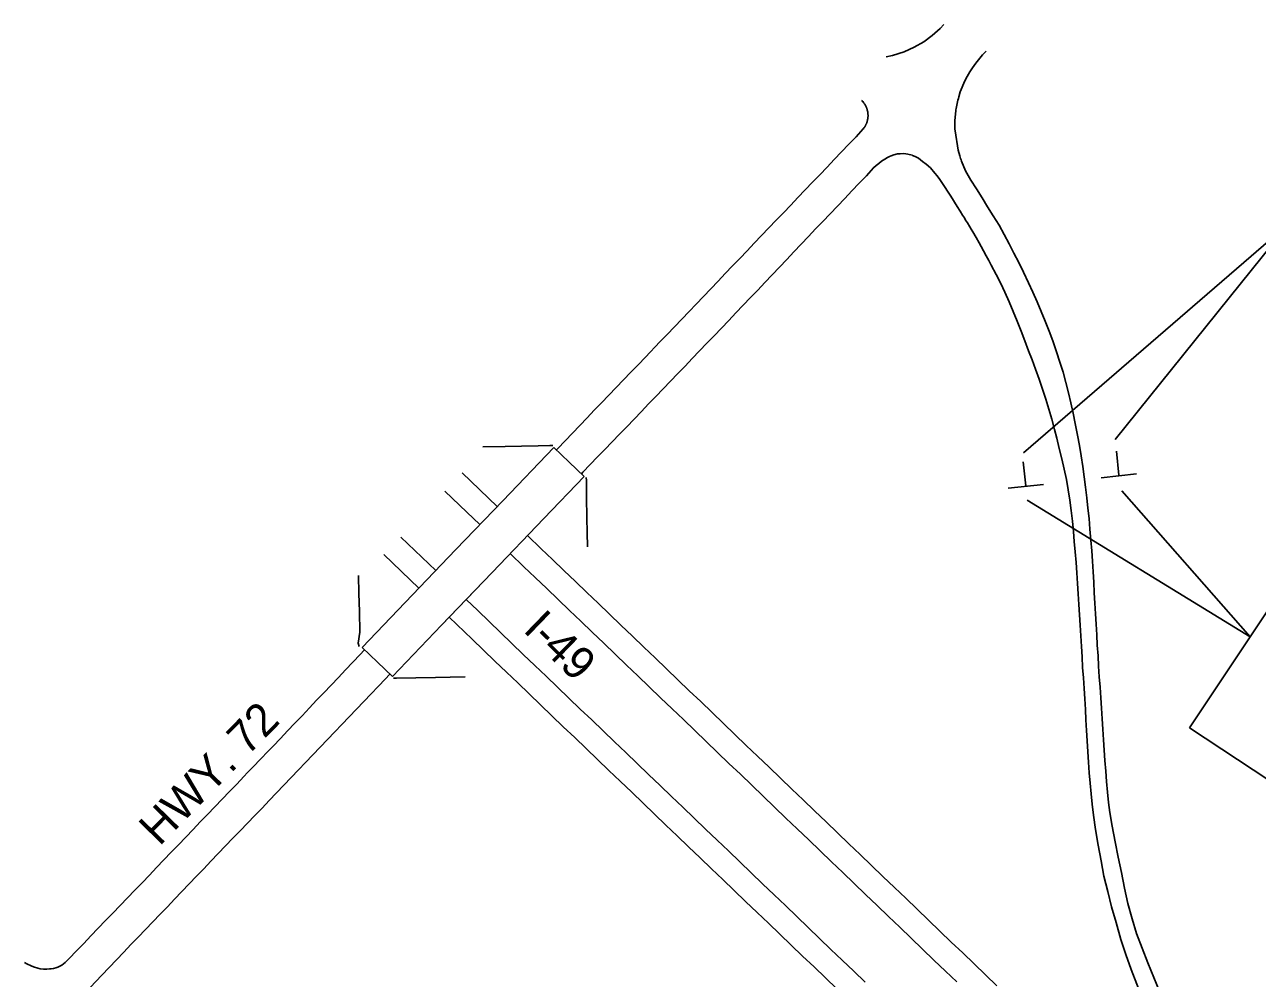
# Model space of a CAD drawing. Extents: x 1017892 to 1236694, y 658811 to 792468.
# Drawn here: x 1021447 to 1022033, y 660033 to 660486 of the extents above; entities that cross this region are included whole.
import ezdxf

# ---------------------------------------------------------------- set-up
doc = ezdxf.new("R2010")
doc.units = 0
for name, color, linetype in [('Level 3', 7, 'Continuous'), ('Level 8', 7, 'Continuous'), ('R_Proposed Road Annot', 7, 'Continuous'), ('S_BRIDGE', 7, 'Continuous'), ('S_CURB', 7, 'Continuous'), ('S_EDGE_PAVEMENT', 7, 'Continuous')]:
    doc.layers.add(name, color=color, linetype=linetype)

msp = doc.modelspace()

# ---------------------------------------------------------------- linework, layer by layer
at = {"layer": 'Level 3'}
for p, q in [((1021967.37, 660271.69), (1021966.17, 660283.15)), ((1021923.15, 660266.71), (1021921.9, 660278.16)), ((1021975.74, 660272.32), (1021958.96, 660270.57)), ((1021931.53, 660267.38), (1021914.75, 660265.54))]:
    msp.add_line(p, q, dxfattribs=at)
at = {"layer": 'Level 8'}
for p in [(1022058.32, 660238.1), (1022087.29, 660094.45)]:
    msp.add_line(p, (1022000.96, 660151.75), dxfattribs=at)
at = {"layer": 'R_Proposed Road Annot'}
for p, q in [((1021922.04, 660282.36), (1022048.03, 660391.35)), ((1021965.64, 660288.67), (1022048.03, 660391.35)), ((1021968.73, 660264.38), (1022029.64, 660194.93)), ((1021923.7, 660259.86), (1022029.64, 660194.93))]:
    msp.add_line(p, q, dxfattribs=at)
at = {"layer": 'S_BRIDGE'}
for p, q in [((1021698.82, 660284.98), (1021674.52, 660259.61)), ((1021698.82, 660284.98), (1021674.52, 660259.61)), ((1021706.09, 660277.95), (1021698.82, 660284.98)), ((1021706.09, 660277.95), (1021698.82, 660284.98)), ((1021713.21, 660271.18), (1021706.09, 660277.95)), ((1021713.21, 660271.18), (1021706.09, 660277.95)), ((1021694.12, 660251.24), (1021713.21, 660271.18)), ((1021694.12, 660251.24), (1021713.21, 660271.18)), ((1021674.52, 660259.61), (1021652.31, 660236.44)), ((1021674.52, 660259.61), (1021652.31, 660236.44)), ((1021669.48, 660225.51), (1021694.12, 660251.24)), ((1021669.48, 660225.51), (1021694.12, 660251.24)), ((1021652.31, 660236.44), (1021628.18, 660211.28)), ((1021652.31, 660236.44), (1021628.18, 660211.28)), ((1021645.49, 660200.48), (1021669.48, 660225.51)), ((1021657.16, 660212.65), (1021669.48, 660225.51)), ((1021628.18, 660211.28), (1021607.71, 660189.93)), ((1021628.18, 660211.28), (1021607.71, 660189.93)), ((1021645.49, 660200.48), (1021657.15, 660212.64)), ((1021622.15, 660176.11), (1021645.49, 660200.48)), ((1021622.15, 660176.11), (1021645.49, 660200.48)), ((1021607.71, 660189.93), (1021615.05, 660182.89)), ((1021607.71, 660189.93), (1021615.05, 660182.89)), ((1021615.05, 660182.89), (1021622.15, 660176.11)), ((1021615.05, 660182.89), (1021622.15, 660176.11))]:
    msp.add_line(p, q, dxfattribs=at)
at = {"layer": 'S_CURB'}
msp.add_line((1021606.62, 660197.13), (1021606.47, 660207.02), dxfattribs=at)
for points in [[(1021665.14, 660285.18), (1021675.69, 660285.41), (1021683.53, 660285.57), (1021691.36, 660285.73), (1021696.95, 660285.81), (1021698.32, 660285.85)], [(1021714.17, 660270.69), (1021714.28, 660269.21), (1021714.28, 660261.37), (1021714.44, 660251.56), (1021714.6, 660244.6), (1021714.77, 660237.65)], [(1021606.37, 660190.37), (1021605.91, 660191.99), (1021606.62, 660197.13), (1021606.47, 660207.02), (1021606.23, 660215.59), (1021606, 660224.16)], [(1021656.73, 660175.89), (1021649.62, 660175.75), (1021642.52, 660175.6), (1021633.33, 660175.44), (1021624.14, 660175.29), (1021622.66, 660175.27)]]:
    msp.add_lwpolyline(points, dxfattribs=at)
at = {"layer": 'S_EDGE_PAVEMENT'}
for points in [[(1021884.16, 660485.81), (1021882.38, 660484.04), (1021878.61, 660480.73), (1021874.62, 660477.64), (1021870.12, 660475.05)], [(1021870.12, 660475.05), (1021865.23, 660472.82), (1021859.81, 660471.12), (1021856.8, 660470.56)], [(1021902.54, 660471.43), (1021899.36, 660467.55), (1021897.84, 660465.33), (1021896.51, 660463.35), (1021895.24, 660461.11), (1021894.01, 660458.82), (1021892.85, 660456.07), (1021891.96, 660453.85)], [(1021902.51, 660471.39), (1021902.54, 660471.43), (1021904.24, 660473.21)], [(1021890.49, 660448.31), (1021890.67, 660449.1), (1021890.86, 660449.88), (1021891.07, 660450.66), (1021891.29, 660451.44)], [(1021891.96, 660453.85), (1021891.29, 660451.44)], [(1021845.84, 660436.25), (1021846.11, 660436.59), (1021846.36, 660436.94), (1021846.6, 660437.31), (1021846.72, 660437.5), (1021846.83, 660437.7), (1021846.94, 660437.89), (1021847.05, 660438.1), (1021847.15, 660438.3), (1021847.25, 660438.51), (1021847.34, 660438.72), (1021847.43, 660438.94), (1021847.51, 660439.16), (1021847.59, 660439.38), (1021847.66, 660439.61), (1021847.73, 660439.84), (1021847.8, 660440.07), (1021847.85, 660440.3), (1021847.91, 660440.53), (1021847.95, 660440.77), (1021848, 660441.01), (1021848.03, 660441.25), (1021848.06, 660441.49), (1021848.09, 660441.73), (1021848.11, 660441.98), (1021848.12, 660442.22), (1021848.12, 660442.47), (1021848.12, 660442.71), (1021848.12, 660442.96), (1021848.11, 660443.2), (1021848.09, 660443.45), (1021848.07, 660443.69), (1021848.04, 660443.94), (1021848, 660444.18), (1021847.96, 660444.42), (1021847.91, 660444.66), (1021847.86, 660444.9), (1021847.8, 660445.13), (1021847.74, 660445.37), (1021847.67, 660445.6), (1021847.59, 660445.83), (1021847.51, 660446.06), (1021847.43, 660446.28), (1021847.34, 660446.5), (1021847.24, 660446.72), (1021847.14, 660446.94), (1021847.04, 660447.15), (1021846.93, 660447.36), (1021846.82, 660447.56), (1021846.7, 660447.76), (1021846.58, 660447.96), (1021846.45, 660448.15), (1021846.33, 660448.34), (1021846.19, 660448.52), (1021846.06, 660448.7), (1021845.92, 660448.88), (1021845.64, 660449.22), (1021845.34, 660449.54), (1021845.04, 660449.84)], [(1021889.57, 660442.24), (1021889.64, 660443.01), (1021889.73, 660443.77), (1021889.82, 660444.53), (1021889.93, 660445.29), (1021890.05, 660446.05), (1021890.19, 660446.8), (1021890.33, 660447.56), (1021890.49, 660448.31)], [(1021889.47, 660435.38), (1021889.43, 660436.23), (1021889.4, 660437.09), (1021889.39, 660437.95), (1021889.4, 660438.81), (1021889.42, 660439.67), (1021889.45, 660440.53), (1021889.5, 660441.39), (1021889.57, 660442.24)], [(1021846.09, 660436.52), (1021845.84, 660436.25), (1021842.44, 660432.59), (1021839.01, 660428.96), (1021835.53, 660425.36), (1021832.09, 660421.75), (1021828.65, 660418.12), (1021825.18, 660414.52), (1021821.7, 660410.93), (1021818.25, 660407.32), (1021814.83, 660403.67), (1021811.37, 660400.07), (1021807.9, 660396.47), (1021804.47, 660392.84), (1021801, 660389.24), (1021797.56, 660385.62), (1021794.1, 660382.01), (1021790.67, 660378.38), (1021787.2, 660374.78), (1021783.75, 660371.16), (1021780.31, 660367.55), (1021776.86, 660363.93), (1021773.43, 660360.29), (1021770, 660356.66), (1021766.53, 660353.07), (1021763.07, 660349.46), (1021759.61, 660345.85), (1021756.15, 660342.25), (1021752.69, 660338.64), (1021749.21, 660335.05), (1021742.32, 660327.81), (1021738.84, 660324.22), (1021735.35, 660320.64), (1021731.91, 660317.01), (1021728.43, 660313.43), (1021724.97, 660309.82), (1021721.52, 660306.2), (1021718.07, 660302.57), (1021714.61, 660298.96), (1021711.16, 660295.35), (1021707.69, 660291.74), (1021704.24, 660288.12), (1021700.78, 660284.51), (1021700.22, 660283.92)], [(1021891.7, 660423.46), (1021890.91, 660426.13), (1021889.47, 660435.38)], [(1021850.75, 660417.72), (1021852.06, 660418.94), (1021853.22, 660419.92), (1021854.58, 660420.98), (1021856.06, 660421.95), (1021857.31, 660422.68), (1021858.41, 660423.24), (1021859.12, 660423.55), (1021860.39, 660423.98), (1021862.12, 660424.4), (1021863.38, 660424.49), (1021865.08, 660424.54), (1021866.98, 660424.24), (1021869.03, 660423.75), (1021869.34, 660423.67), (1021870.6, 660423.13), (1021872.07, 660422.32), (1021873.03, 660421.59), (1021874.07, 660420.87), (1021875.7, 660419.56), (1021877.87, 660417.75), (1021879.9, 660415.32), (1021880.99, 660414.01), (1021882.29, 660412.22), (1021883.85, 660409.9), (1021884.76, 660408.36), (1021885.92, 660406.69), (1021886.51, 660405.67), (1021887.13, 660404.85), (1021888.24, 660403.04), (1021889.26, 660401.48), (1021890.48, 660399.47), (1021891.93, 660397.24), (1021893.08, 660395.3), (1021893.95, 660394), (1021894.52, 660392.98), (1021895.32, 660391.73), (1021896.48, 660389.79), (1021897.13, 660388.71), (1021897.9, 660387.41), (1021899.44, 660384.64), (1021900.93, 660382.12), (1021901.93, 660380.33), (1021902.97, 660378.42), (1021904.29, 660375.92), (1021905.47, 660373.78), (1021906.66, 660371.52), (1021908.98, 660367.08), (1021911.16, 660362.76), (1021913.15, 660358.68), (1021915.17, 660354.11), (1021917.13, 660349.51), (1021919.04, 660344.89), (1021920.87, 660340.23), (1021922.67, 660335.57), (1021924.41, 660330.88), (1021926.07, 660326.57), (1021927.72, 660322.1), (1021929.39, 660317.38), (1021930.97, 660312.63), (1021932.55, 660307.88), (1021934.05, 660303.11), (1021935.43, 660298.31), (1021936.7, 660293.52), (1021937.8, 660289.32), (1021939.03, 660284.45), (1021940.21, 660279.57), (1021941.37, 660274.68), (1021942.39, 660269.78), (1021943.29, 660264.86), (1021944.04, 660259.91), (1021944.7, 660254.95), (1021945.27, 660249.98), (1021945.78, 660245.03), (1021946.16, 660240.31), (1021946.53, 660235.32), (1021946.96, 660230.34), (1021947.31, 660225.35), (1021947.69, 660220.36), (1021948, 660215.37), (1021948.31, 660210.39), (1021948.65, 660205.4), (1021949, 660200.42), (1021949.33, 660195.43), (1021949.61, 660190.44), (1021949.89, 660185.44), (1021950.12, 660180.45), (1021950.51, 660175.46), (1021950.79, 660170.47), (1021951.13, 660165.48), (1021951.42, 660160.49), (1021951.7, 660155.5), (1021951.98, 660150.5), (1021952.34, 660145.52), (1021952.59, 660140.39), (1021952.91, 660135.38), (1021953.24, 660130.39), (1021953.61, 660125.4), (1021954.12, 660120.43), (1021954.6, 660115.45), (1021955.23, 660110.24), (1021956.26, 660103.35)], [(1021892.56, 660421), (1021892.33, 660421.62), (1021892.11, 660422.24), (1021891.89, 660422.87), (1021891.68, 660423.5)], [(1021712.1, 660272.57), (1021712.67, 660273.18), (1021716.12, 660276.79), (1021719.58, 660280.41), (1021723.04, 660284.01), (1021726.5, 660287.62), (1021729.96, 660291.23), (1021733.45, 660294.79), (1021736.93, 660298.38), (1021740.41, 660301.97), (1021743.85, 660305.59), (1021747.3, 660309.2), (1021750.76, 660312.82), (1021754.24, 660316.41), (1021757.71, 660320.01), (1021761.16, 660323.61), (1021764.62, 660327.22), (1021768.1, 660330.82), (1021771.55, 660334.43), (1021775.01, 660338.04), (1021778.46, 660341.64), (1021781.92, 660345.25), (1021785.38, 660348.86), (1021788.84, 660352.46), (1021792.26, 660356.11), (1021795.71, 660359.72), (1021799.17, 660363.33), (1021802.62, 660366.95), (1021806.04, 660370.59), (1021809.48, 660374.21), (1021812.93, 660377.83), (1021816.38, 660381.44), (1021819.77, 660385.11), (1021823.22, 660388.74), (1021826.72, 660392.31), (1021830.13, 660395.96), (1021833.58, 660399.57), (1021837.05, 660403.16), (1021840.44, 660406.84), (1021843.89, 660410.46), (1021847.35, 660414.06), (1021850.75, 660417.72), (1021851.37, 660418.37)], [(1021964.07, 660104.97), (1021962.96, 660111.43), (1021962.43, 660116.25), (1021961.86, 660121.22), (1021961.42, 660126.2), (1021961.08, 660131.19), (1021960.72, 660136.18), (1021960.31, 660141.15), (1021960, 660146.03), (1021959.69, 660151.03), (1021959.33, 660156.01), (1021959.01, 660161), (1021958.7, 660165.99), (1021958.4, 660170.98), (1021958.04, 660175.97), (1021957.69, 660180.96), (1021957.46, 660185.95), (1021957.01, 660190.93), (1021956.81, 660195.93), (1021956.54, 660200.93), (1021956.2, 660205.91), (1021955.91, 660210.91), (1021955.66, 660215.91), (1021955.42, 660220.9), (1021955.16, 660225.9), (1021954.86, 660230.89), (1021954.48, 660235.87), (1021954.08, 660240.86), (1021953.6, 660246.11), (1021953.17, 660251.13), (1021952.57, 660256.09), (1021952.06, 660261.07), (1021951.52, 660266.04), (1021950.9, 660271), (1021950.19, 660275.95), (1021949.38, 660280.89), (1021948.58, 660285.82), (1021947.67, 660290.74), (1021946.63, 660296.25), (1021945.6, 660301.21), (1021944.5, 660306.1), (1021943.32, 660310.96), (1021942.13, 660315.82), (1021940.8, 660320.64), (1021939.32, 660325.42), (1021937.7, 660330.42), (1021935.92, 660335.51), (1021934.19, 660340.21), (1021932.37, 660344.86), (1021930.48, 660349.49), (1021928.53, 660354.1), (1021926.47, 660358.66), (1021924.4, 660363.22), (1021922.03, 660368.15), (1021919.72, 660372.77), (1021917.48, 660377.24), (1021915.21, 660381.69), (1021912.79, 660386.07), (1021910.42, 660390.5), (1021907.61, 660395.04), (1021904.96, 660399.28), (1021902.31, 660403.52), (1021899.61, 660407.73), (1021896.95, 660411.96), (1021894.49, 660416.32), (1021892.56, 660421)], [(1021655.25, 660272.8), (1021671.89, 660256.86)], [(1021663.68, 660248.3), (1021657.52, 660254.2), (1021647.04, 660264.24)], [(1021626.1, 660242.38), (1021642.74, 660226.45)], [(1021686.29, 660243.07), (1021692.81, 660236.82), (1021698.22, 660231.63), (1021703.64, 660226.45), (1021709.06, 660221.26), (1021714.47, 660216.07), (1021719.89, 660210.88), (1021725.3, 660205.69), (1021730.72, 660200.5), (1021736.14, 660195.31), (1021741.55, 660190.12), (1021746.96, 660184.93), (1021752.38, 660179.74), (1021757.79, 660174.55), (1021763.2, 660169.36), (1021768.62, 660164.17), (1021774.03, 660158.98), (1021779.44, 660153.79), (1021784.85, 660148.59), (1021790.27, 660143.4), (1021795.68, 660138.21), (1021801.1, 660133.02), (1021806.51, 660127.83), (1021811.92, 660122.64), (1021817.34, 660117.45), (1021822.75, 660112.25), (1021828.16, 660107.06), (1021833.58, 660101.87), (1021838.99, 660096.68), (1021844.4, 660091.49), (1021849.81, 660086.29), (1021855.22, 660081.1), (1021860.64, 660075.91), (1021866.05, 660070.72), (1021871.46, 660065.53), (1021876.87, 660060.34), (1021882.28, 660055.14), (1021887.7, 660049.95), (1021893.11, 660044.76), (1021898.52, 660039.57), (1021903.93, 660034.37), (1021909.34, 660029.18)], [(1021890.28, 660030.97), (1021884.87, 660036.17), (1021879.46, 660041.36), (1021874.05, 660046.55), (1021868.64, 660051.75), (1021863.23, 660056.94), (1021857.82, 660062.13), (1021852.4, 660067.33), (1021846.99, 660072.52), (1021841.58, 660077.72), (1021836.17, 660082.91), (1021830.76, 660088.1), (1021825.35, 660093.3), (1021819.93, 660098.49), (1021814.52, 660103.68), (1021809.11, 660108.88), (1021803.7, 660114.07), (1021798.29, 660119.26), (1021792.88, 660124.45), (1021787.46, 660129.64), (1021782.05, 660134.84), (1021776.64, 660140.03), (1021771.23, 660145.22), (1021765.82, 660150.41), (1021760.41, 660155.61), (1021754.99, 660160.8), (1021749.58, 660165.99), (1021744.17, 660171.18), (1021738.76, 660176.38), (1021733.35, 660181.57), (1021727.93, 660186.76), (1021722.52, 660191.95), (1021717.1, 660197.14), (1021711.69, 660202.33), (1021706.27, 660207.51), (1021700.85, 660212.7), (1021695.44, 660217.89), (1021690.02, 660223.07), (1021684.6, 660228.26), (1021678.09, 660234.5)], [(1021634.69, 660218.07), (1021618.07, 660234.01)], [(1021657.16, 660212.65), (1021662.66, 660207.39), (1021668.08, 660202.2), (1021673.49, 660197.02), (1021678.9, 660191.82), (1021684.31, 660186.62), (1021689.73, 660181.41), (1021695.14, 660176.21), (1021700.54, 660171.02), (1021705.97, 660165.83), (1021711.39, 660160.65), (1021716.81, 660155.48), (1021722.22, 660150.3), (1021727.64, 660145.11), (1021733.06, 660139.93), (1021738.47, 660134.73), (1021743.88, 660129.54), (1021749.3, 660124.34), (1021754.71, 660119.15), (1021760.12, 660113.96), (1021765.54, 660108.77), (1021770.96, 660103.59), (1021776.37, 660098.4), (1021781.79, 660093.21), (1021787.21, 660088.02), (1021792.63, 660082.84), (1021798.04, 660077.65), (1021803.45, 660072.45), (1021808.85, 660067.26), (1021814.26, 660062.07), (1021819.67, 660056.87), (1021825.08, 660051.68), (1021830.49, 660046.48), (1021835.91, 660041.29), (1021841.33, 660036.1), (1021846.74, 660030.92)], [(1021833.31, 660027.74), (1021827.9, 660032.92), (1021822.48, 660038.11), (1021817.06, 660043.29), (1021811.64, 660048.48), (1021806.22, 660053.66), (1021800.8, 660058.85), (1021795.38, 660064.04), (1021789.95, 660069.22), (1021784.54, 660074.41), (1021779.12, 660079.6), (1021773.71, 660084.79), (1021768.29, 660089.98), (1021762.88, 660095.17), (1021757.47, 660100.36), (1021752.05, 660105.55), (1021746.64, 660110.74), (1021741.23, 660115.93), (1021735.82, 660121.12), (1021730.4, 660126.31), (1021724.99, 660131.5), (1021719.58, 660136.69), (1021714.16, 660141.88), (1021708.74, 660147.08), (1021703.33, 660152.27), (1021697.91, 660157.46), (1021692.5, 660162.66), (1021687.08, 660167.84), (1021681.67, 660173.03), (1021676.27, 660178.21), (1021670.85, 660183.4), (1021665.44, 660188.59), (1021660.02, 660193.78), (1021649.1, 660204.25)], [(1021465.09, 660039.03), (1021466.58, 660040.22), (1021466.87, 660040.49), (1021468.51, 660042.11), (1021471.98, 660045.71), (1021475.43, 660049.33), (1021478.88, 660052.95), (1021485.82, 660060.14), (1021489.29, 660063.74), (1021492.74, 660067.35), (1021496.21, 660070.95), (1021499.65, 660074.58), (1021503.15, 660078.15), (1021506.63, 660081.73), (1021510.06, 660085.36), (1021513.52, 660088.97), (1021516.99, 660092.57), (1021520.44, 660096.18), (1021523.92, 660099.77), (1021527.38, 660103.38), (1021530.83, 660106.99), (1021534.3, 660110.59), (1021537.76, 660114.2), (1021541.22, 660117.8), (1021544.67, 660121.42), (1021548.14, 660125.02), (1021551.59, 660128.64), (1021553.31, 660130.43), (1021555.04, 660132.25), (1021556.86, 660134.2), (1021558.49, 660135.86), (1021560.55, 660137.91), (1021561.97, 660139.45), (1021565.42, 660143.07), (1021568.87, 660146.69), (1021572.34, 660150.28), (1021575.81, 660153.89), (1021579.26, 660157.5), (1021582.66, 660161.16), (1021586.1, 660164.8), (1021589.56, 660168.4), (1021593.02, 660172.01), (1021596.46, 660175.63), (1021599.9, 660179.27), (1021603.35, 660182.89), (1021606.78, 660186.52), (1021608.75, 660188.59)], [(1021620.77, 660177.12), (1021618.87, 660175.05), (1021615.42, 660171.43), (1021611.99, 660167.8), (1021608.5, 660164.22), (1021605.04, 660160.61), (1021601.6, 660156.98), (1021598.13, 660153.38), (1021594.69, 660149.76), (1021591.23, 660146.15), (1021587.78, 660142.53), (1021584.33, 660138.92), (1021580.88, 660135.29), (1021577.42, 660131.69), (1021573.96, 660128.09), (1021570.52, 660124.45), (1021567.06, 660120.85), (1021563.59, 660117.25), (1021560.16, 660113.61), (1021556.7, 660110.01), (1021553.22, 660106.42), (1021549.73, 660102.84), (1021546.29, 660099.22), (1021542.84, 660095.6), (1021539.38, 660091.99), (1021535.91, 660088.4), (1021532.45, 660084.8), (1021529.01, 660081.17), (1021525.52, 660077.59), (1021522.06, 660073.99), (1021518.62, 660070.35), (1021515.17, 660066.74), (1021511.7, 660063.15), (1021508.23, 660059.55), (1021504.77, 660055.94), (1021501.33, 660052.32), (1021497.87, 660048.71), (1021494.45, 660045.06), (1021490.94, 660041.51), (1021487.51, 660037.87), (1021484.05, 660034.26), (1021478.43, 660028.34)], [(1022018.59, 659952.41), (1022015.6, 659956.52), (1022011.4, 659962.74), (1022007.2, 659968.96), (1022003.22, 659975.32), (1021999.23, 659981.67), (1021995.56, 659988.22), (1021991.89, 659994.76), (1021988.36, 660001.85), (1021984.66, 660009.25), (1021981.6, 660016.11), (1021978.54, 660022.97), (1021975.83, 660029.96), (1021973.11, 660036.94), (1021970.7, 660044.05), (1021968.28, 660051.15), (1021966, 660059.16), (1021963.87, 660066.63), (1021962.06, 660073.91), (1021960.25, 660081.2), (1021958.86, 660088.57), (1021957.48, 660095.94), (1021956.26, 660103.35)], [(1021964.07, 660104.97), (1021965.55, 660097.62), (1021967.04, 660090.27), (1021968.53, 660082.92), (1021970.02, 660075.57), (1021971.51, 660068.22), (1021973.6, 660061.05), (1021975.66, 660054), (1021978.41, 660047.02), (1021981.16, 660040.05), (1021983.92, 660033.07), (1021986.75, 660026.12), (1021989.59, 660019.18), (1021992.43, 660012.23), (1021995.87, 660005.85), (1021999.37, 659999.37), (1022002.93, 659992.76), (1022006.8, 659986.33), (1022010.67, 659979.91), (1022014.54, 659973.49), (1022018.71, 659967.24), (1022024.49, 659958.6)], [(1021447.37, 660040.21), (1021448.36, 660039.64), (1021450.44, 660038.6), (1021451.59, 660038.15), (1021453.56, 660037.49), (1021454.73, 660037.27), (1021456.33, 660037.11), (1021457.96, 660037.06), (1021459.21, 660037.17), (1021459.99, 660037.22), (1021461.08, 660037.42), (1021462.22, 660037.72), (1021463.19, 660038.06), (1021464.12, 660038.45), (1021464.75, 660038.8), (1021465.09, 660039.03)]]:
    msp.add_lwpolyline(points, dxfattribs=at)

# ---------------------------------------------------------------- texts
at = {"layer": 'R_Proposed Road Annot'}
for s, rotation, p in [('I-49', 315.93487, (1021683.72, 660197.84)), ('HWY. 72', 45.73015, (1021511.44, 660095.14))]:
    msp.add_text(s, height=15.5, rotation=rotation, dxfattribs=at).set_placement(p)

doc.saveas('drawing.dxf')
